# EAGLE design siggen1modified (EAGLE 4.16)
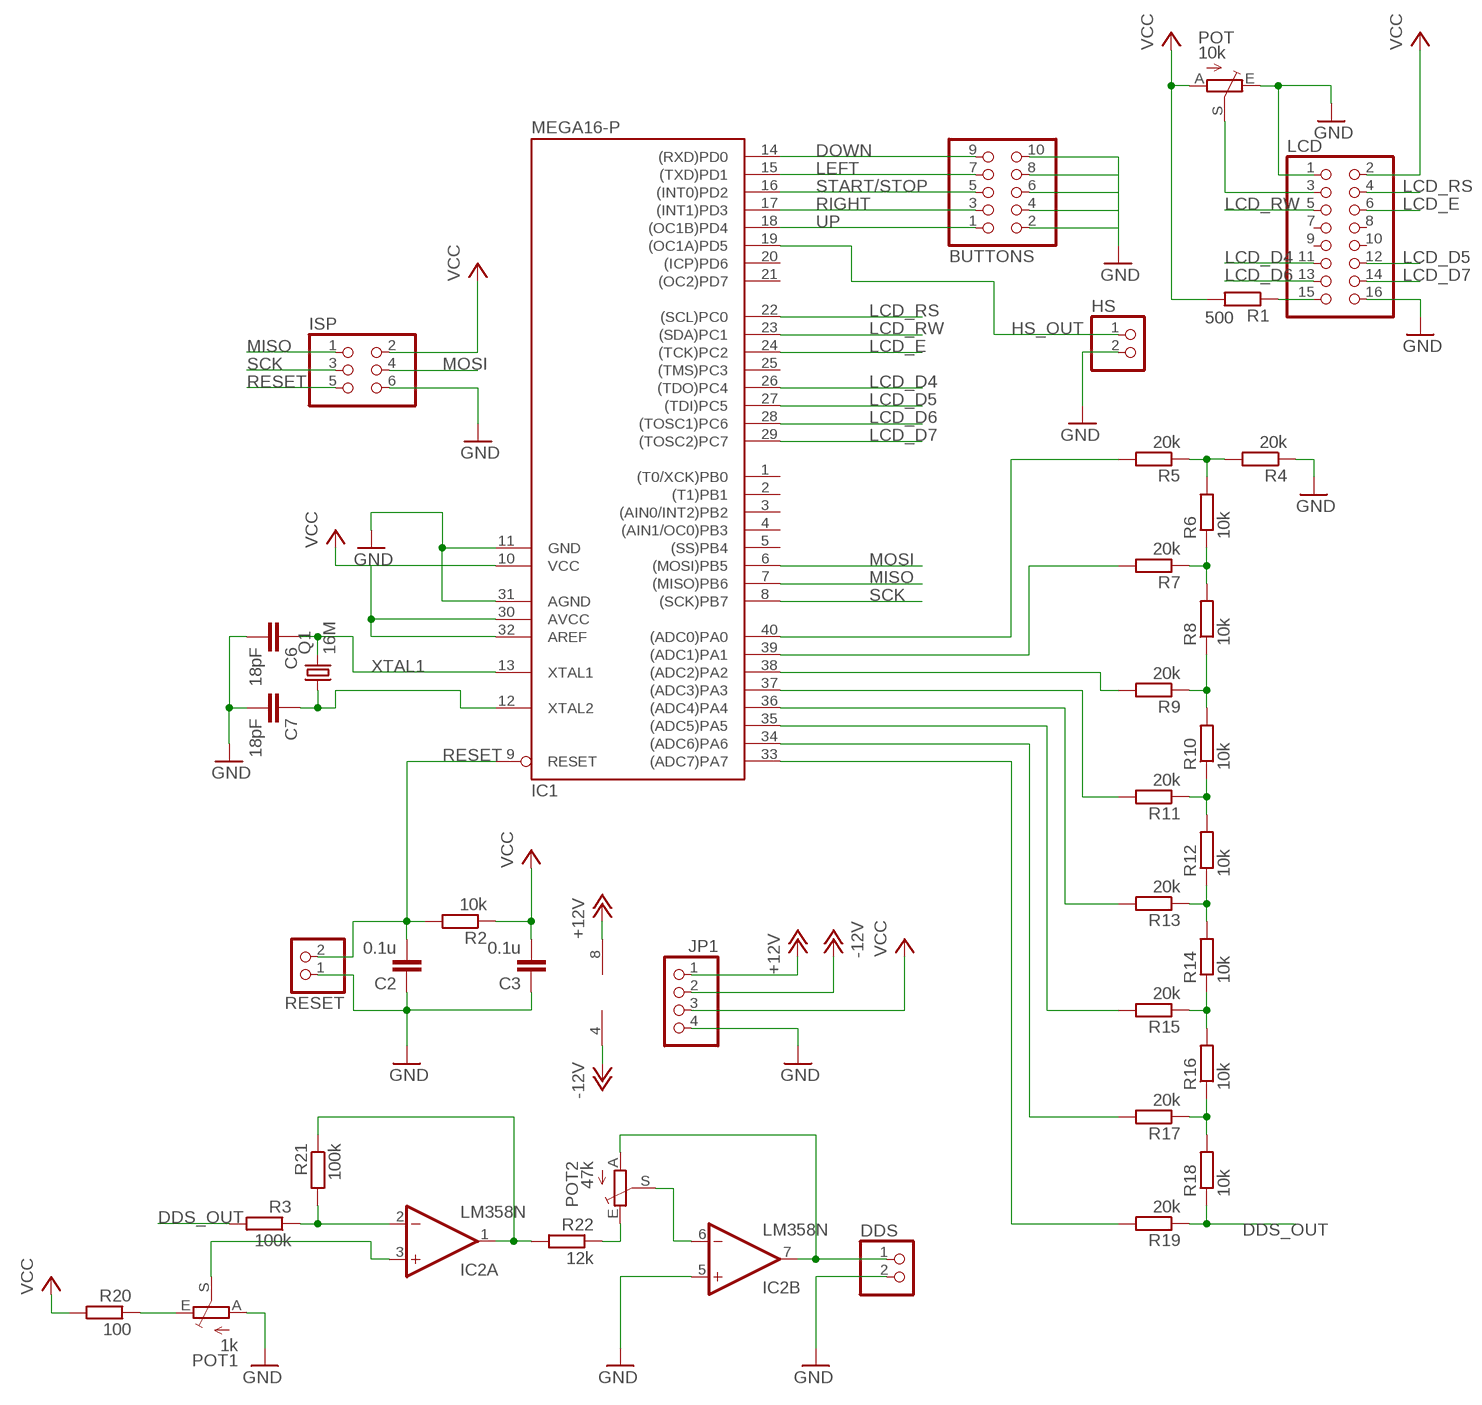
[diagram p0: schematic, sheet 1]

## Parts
BUTTONS  PINHD-2X5  [2X05]
C2  0.1u  C-EUC0805  [C0805]
C3  0.1u  C-EUC0805  [C0805]
C6  18pF  C-EUC0805  [C0805]
C7  18pF  C-EUC0805  [C0805]
DDS  PINHD-1X2  [1X02]
HS  PINHD-1X2  [1X02]
IC1  MEGA16-P  [DIL40]
IC2  LM358N  [DIL08]
ISP  PINHD-2X3  [2X03]
JP1  PINHD-1X4  [1X04]
LCD  PINHD-2X8  [2X08]
POT  10k  TRIM_EU-B64W  [B64W]
POT1  1k  TRIM_EU-B64W  [B64W]
POT2  47k  TRIM_EU-B64W  [B64W]
Q1  16M  CRYTALHC49S  [HC49/S]
R1  500  R-EU_M0805  [M0805]
R2  10k  R-EU_R0805  [R0805]
R3  100k  R-EU_M0805  [M0805]
R4  20k  R-EU_M0805  [M0805]
R5  20k  R-EU_M0805  [M0805]
R6  10k  R-EU_M0805  [M0805]
R7  20k  R-EU_M0805  [M0805]
R8  10k  R-EU_M0805  [M0805]
R9  20k  R-EU_M0805  [M0805]
R10  10k  R-EU_M0805  [M0805]
R11  20k  R-EU_M0805  [M0805]
R12  10k  R-EU_M0805  [M0805]
R13  20k  R-EU_M0805  [M0805]
R14  10k  R-EU_M0805  [M0805]
R15  20k  R-EU_M0805  [M0805]
R16  10k  R-EU_M0805  [M0805]
R17  20k  R-EU_M0805  [M0805]
R18  10k  R-EU_M0805  [M0805]
R19  20k  R-EU_M0805  [M0805]
R20  100  R-EU_M0805  [M0805]
R21  100k  R-EU_M0805  [M0805]
R22  12k  R-EU_M0805  [M0805]
RESET  PINHD-1X2  [1X02]

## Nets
+12V: IC2.8(P:V+) JP1.1
-12V: IC2.4(P:V-) JP1.2
DDS_OUT: R3.2 R18.1 R19.1
DOWN: BUTTONS.9 IC1.14((RXD)PD0)
GND: BUTTONS.2 BUTTONS.4 BUTTONS.6 BUTTONS.8 BUTTONS.10 C2.1 C3.1 C6.2 C7.2 DDS.2 HS.2 IC1.11(GND) IC1.31(AGND) IC2.5(B:+IN) ISP.6 JP1.4 LCD.1 LCD.16 POT1.A POT.E R4.1 RESET.1
HS_OUT: HS.1 IC1.19((OC1A)PD5)
LCD_D4: IC1.26((TDO)PC4) LCD.11
LCD_D5: IC1.27((TDI)PC5) LCD.12
LCD_D6: IC1.28((TOSC1)PC6) LCD.13
LCD_D7: IC1.29((TOSC2)PC7) LCD.14
LCD_E: IC1.24((TCK)PC2) LCD.6
LCD_RS: IC1.22((SCL)PC0) LCD.4
LCD_RW: IC1.23((SDA)PC1) LCD.5
LEFT: BUTTONS.7 IC1.15((TXD)PD1)
MISO: IC1.7((MISO)PB6) ISP.1
MOSI: IC1.6((MOSI)PB5) ISP.4
N$1: IC1.40((ADC0)PA0) R5.2
N$2: LCD.3 POT.S
N$3: IC2.2(A:-IN) R3.1 R21.2
N$5: LCD.15 R1.1
N$6: IC1.39((ADC1)PA1) R7.2
N$7: IC1.33((ADC7)PA7) R19.2
N$8: IC1.34((ADC6)PA6) R17.2
N$9: IC1.35((ADC5)PA5) R15.2
N$10: IC1.36((ADC4)PA4) R13.2
N$11: IC1.37((ADC3)PA3) R11.2
N$12: IC1.38((ADC2)PA2) R9.2
N$13: POT2.E R22.1
N$14: IC2.3(A:+IN) POT1.S
N$15: R4.2 R5.1 R6.2
N$16: IC2.1(A:OUT) R21.1 R22.2
N$17: POT1.E R20.1
N$18: R6.1 R7.1 R8.2
N$19: DDS.1 IC2.7(B:OUT) POT2.A
N$20: R8.1 R9.1 R10.2
N$21: R10.1 R11.1 R12.2
N$22: R12.1 R13.1 R14.2
N$23: R14.1 R15.1 R16.2
N$24: R16.1 R17.1 R18.2
N$25: IC2.6(B:-IN) POT2.S
N$29: C7.1 IC1.12(XTAL2) Q1.1
RESET: C2.2 IC1.9(RESET) ISP.5 R2.2 RESET.2
RIGHT: BUTTONS.3 IC1.17((INT1)PD3)
SCK: IC1.8((SCK)PB7) ISP.3
START/STOP: BUTTONS.5 IC1.16((INT0)PD2)
UP: BUTTONS.1 IC1.18((OC1B)PD4)
VCC: C3.2 IC1.10(VCC) IC1.30(AVCC) IC1.32(AREF) ISP.2 JP1.3 LCD.2 POT.A R1.2 R2.1 R20.2
XTAL1: C6.1 IC1.13(XTAL1) Q1.2
Unconnected: IC1.1((T0/XCK)PB0) IC1.2((T1)PB1) IC1.3((AIN0/INT2)PB2) IC1.4((AIN1/OC0)PB3) IC1.5((SS)PB4) IC1.20((ICP)PD6) IC1.21((OC2)PD7) IC1.25((TMS)PC3) LCD.7 LCD.8 LCD.9 LCD.10

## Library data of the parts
BUTTONS = pinhead:PINHD-2X5: PIN HEADER
C2 C3 C6 C7 = rcl:C-EU: CAPACITOR, European symbol
DDS HS RESET = pinhead:PINHD-1X2: PIN HEADER
IC1 = atmel:MEGA16-P: MICROCONTROLLER 16 Kbytes FLASH 1 kbytes SRAM 512 bytes EEPROM USART 8-channel 10 bit ADC Source: avr.lbr
IC2 = linear:LM358: OP AMP also LM158; LM258; LM2904 Source: http://cache.national.com/ds/LM/LM158.pdf
ISP = pinhead:PINHD-2X3: PIN HEADER
JP1 = pinhead:PINHD-1X4: PIN HEADER
LCD = pinhead:PINHD-2X8: PIN HEADER
POT POT1 POT2 = pot:TRIM_EU-: POTENTIOMETER
Q1 = crystal:CRYTAL: CRYSTAL
R1-R22 = rcl:R-EU_: RESISTOR, European symbol

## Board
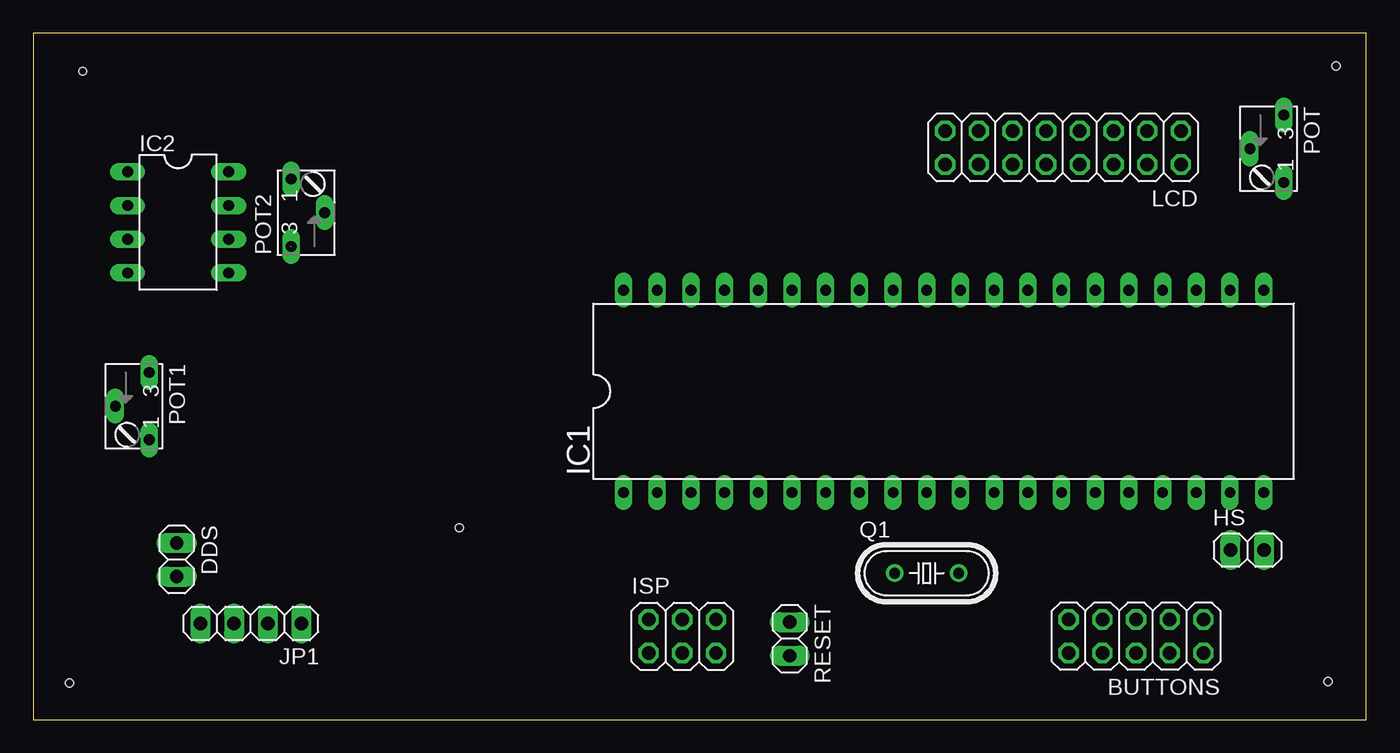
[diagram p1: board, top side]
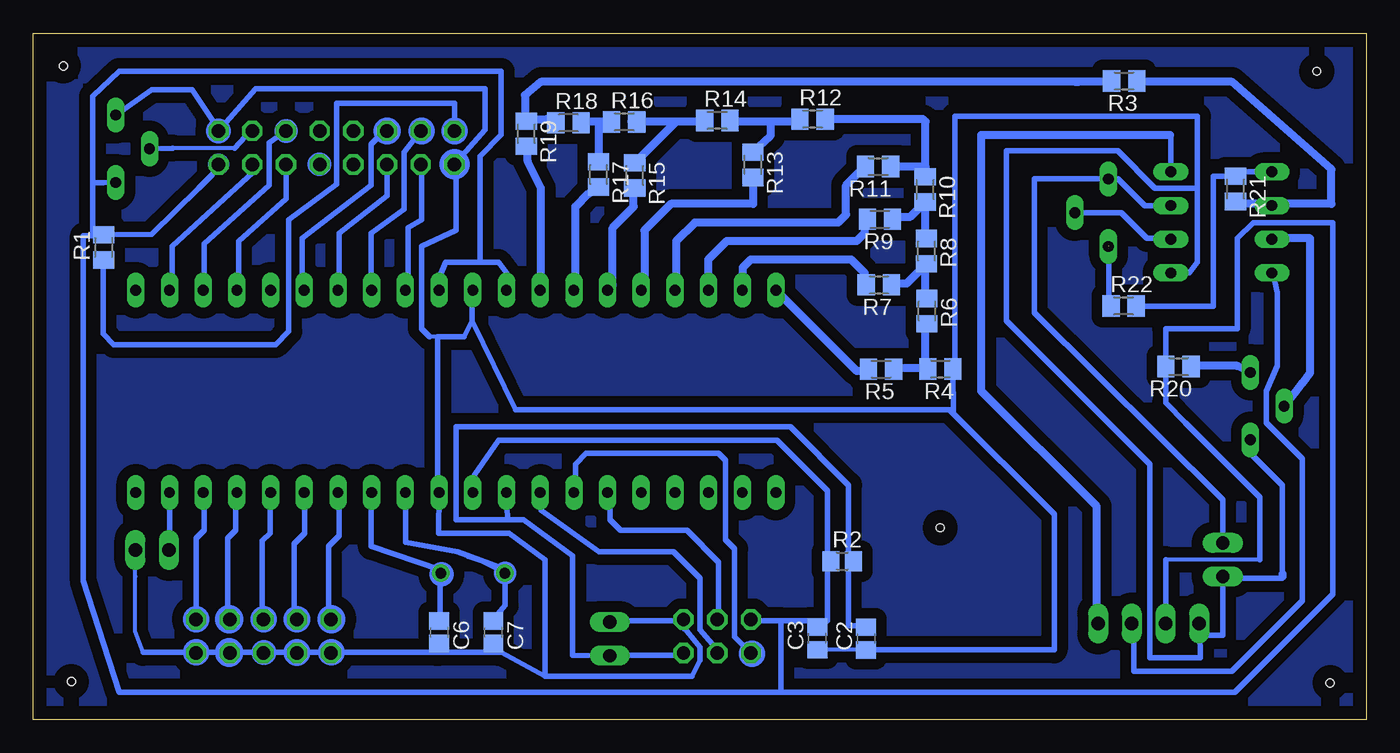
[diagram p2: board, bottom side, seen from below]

Size 100.51 x 51.74 mm. Coordinates in mm from the lower left corner, seen from the top.
Outline: 0,0 100.51,0 100.51,51.74 0,51.74 0,0
Copper layers (1*16): Top 0.035mm / dielectric 1.5mm / Bottom 0.035mm
Design rules "default": minimum track width 10mil, minimum drill 24mil, track to track 8mil, track to pad 8mil, pad to pad 8mil, via to via 8mil, smd to smd 8mil, copper to edge 40mil, drill to drill 8mil, minimum pad ring 10mil, minimum via ring 8mil, stop-mask expansion 4mil, vias tented up to drill 0mil, thermal gap 10mil
Holes 0.6 mm at 32.13,14.47 97.63,2.87 32.13,14.47 98.23,49.27 3.73,48.87 2.73,2.77 98.23,49.27 97.63,2.87

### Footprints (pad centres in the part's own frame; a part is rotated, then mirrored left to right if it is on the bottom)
2X05 = drill 1.016 octagon: 1 -5.08,-1.27; 2 -5.08,1.27; 3 -2.54,-1.27; 4 -2.54,1.27; 5 0,-1.27; 6 0,1.27; 7 2.54,-1.27; 8 2.54,1.27; 9 5.08,-1.27; 10 5.08,1.27
C0805 = smd 1.3 x 1.5: 1 -0.85,0; 2 0.85,0
1X02 = drill 1.016 long: 1 -1.27,0; 2 1.27,0
DIL40 = drill 0.813 long: 1 -24.13,-7.62; 2 -21.59,-7.62; 3 -19.05,-7.62; 4 -16.51,-7.62; 5 -13.97,-7.62; 6 -11.43,-7.62; 7 -8.89,-7.62; 8 -6.35,-7.62; 9 -3.81,-7.62; 10 -1.27,-7.62; 11 1.27,-7.62; 12 3.81,-7.62; 13 6.35,-7.62; 14 8.89,-7.62; 15 11.43,-7.62; 16 13.97,-7.62; 17 16.51,-7.62; 18 19.05,-7.62; 19 21.59,-7.62; 20 24.13,-7.62; 21 24.13,7.62; 22 21.59,7.62; 23 19.05,7.62; 24 16.51,7.62; 25 13.97,7.62; 26 11.43,7.62; 27 8.89,7.62; 28 6.35,7.62; 29 3.81,7.62; 30 1.27,7.62; 31 -1.27,7.62; 32 -3.81,7.62; 33 -6.35,7.62; 34 -8.89,7.62; 35 -11.43,7.62; 36 -13.97,7.62; 37 -16.51,7.62; 38 -19.05,7.62; 39 -21.59,7.62; 40 -24.13,7.62
DIL08 = drill 0.813 long: 1 -3.81,-3.81; 2 -1.27,-3.81; 3 1.27,-3.81; 4 3.81,-3.81; 5 3.81,3.81; 6 1.27,3.81; 7 -1.27,3.81; 8 -3.81,3.81
2X03 = drill 1.016 octagon: 1 -2.54,-1.27; 2 -2.54,1.27; 3 0,-1.27; 4 0,1.27; 5 2.54,-1.27; 6 2.54,1.27
1X04 = drill 1.016 long: 1 -3.81,0; 2 -1.27,0; 3 1.27,0; 4 3.81,0
2X08 = drill 1.016 octagon: 1 -8.89,-1.27; 2 -8.89,1.27; 3 -6.35,-1.27; 4 -6.35,1.27; 5 -3.81,-1.27; 6 -3.81,1.27; 7 -1.27,-1.27; 8 -1.27,1.27; 9 1.27,-1.27; 10 1.27,1.27; 11 3.81,-1.27; 12 3.81,1.27; 13 6.35,-1.27; 14 6.35,1.27; 15 8.89,-1.27; 16 8.89,1.27
B64W = drill 0.813 long: A 2.54,0; E -2.54,0; S 0,-2.54
HC49/S = drill 0.813 round: 1 -2.413,0; 2 2.413,0
M0805 = smd 1.3 x 1.6: 1 -0.95,0; 2 0.95,0
R0805 = smd 1.3 x 1.5: 1 -0.85,0; 2 0.85,0

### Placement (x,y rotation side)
BUTTONS  83.15,6.29 180 top
C2  37.72,6.11 90 bottom
C3  41.39,6.13 90 bottom
C6  69.9,6.59 270 bottom
C7  65.82,6.59 270 bottom
DDS  10.82,12.06 270 top
HS  91.54,12.78 0 top
IC1  68.64,24.75 0 top
IC2  10.93,37.48 270 top
ISP  48.94,6.29 0 top
JP1  16.41,7.25 180 top
LCD  77.64,43.11 180 top
POT  94.28,43.03 270 top
POT1  8.74,23.63 270 top
POT2  19.44,38.21 90 top
Q1  67.36,11.04 0 top
R1  95.2,35.6 90 bottom
R2  39.51,11.95 0 bottom
R3  18.26,48.14 180 bottom
R4  32.11,26.43 180 bottom
R5  36.59,26.41 180 bottom
R6  33.13,30.8 270 bottom
R7  36.75,32.77 180 bottom
R8  33.17,35.31 270 bottom
R9  36.67,37.71 180 bottom
R10  33.26,39.97 270 bottom
R11  36.81,41.69 180 bottom
R12  41.75,45.26 0 bottom
R13  46.25,41.82 270 bottom
R14  48.93,45.16 0 bottom
R15  55.15,41.02 270 bottom
R16  55.95,45.04 0 bottom
R17  57.89,41.1 270 bottom
R18  60.16,44.98 0 bottom
R19  63.33,44.16 270 bottom
R20  14.16,26.62 180 bottom
R21  9.86,40 270 bottom
R22  18.3,31.18 0 bottom
RESET  57.04,6.09 270 top

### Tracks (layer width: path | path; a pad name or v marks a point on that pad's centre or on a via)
+12V
  Bottom 0.406: IC2.8 14.73,44.07 14.78,44.07
  Bottom 0.61: 14.78,44.07 29.03,44.07 29.03,24.77 20.33,16.07 20.33,6.24 | 20.33,6.24 20.33,6.17 | JP1.1 20.33,6.24
-12V
  Bottom 0.305: 17.53,6.4 JP1.2 | 7.03,33.57 6.98,33.67
  Bottom 0.406: 17.53,6.4 17.53,3.67 10.13,3.67 4.83,8.97 4.83,19.67 7.53,22.37 7.53,24.77 6.73,26.67 6.73,32.17 7.03,33.57 IC2.4
DDS_OUT
  Bottom 0.61: R18.1 61.8,45.27 63.37,45.27 R19.1 63.29,45.07 63.43,45.07 63.43,47.07 62.23,48.07 21.93,48.07 | 21.93,48.07 21.74,48.07 | R3.2 19.28,48.07 21.93,48.07
DOWN
  Bottom 0.305: BUTTONS.9 78.23,7.72 | 77.43,17.07 77.47,17.07 IC1.14
  Bottom 0.406: 78.23,7.72 78.23,13.07 77.43,13.87 77.43,17.07
GND
  Bottom 0.254: C7.2 65.43,5.07 | C6.2 69.93,5.07 | 77.43,5.07 BUTTONS.10 | 51.23,6.67 51.43,6.87 | 31.03,27.17 R4.1
  Bottom 0.305: IC1.31 67.43,31.31 67.43,30.07 | 70.03,28.87 70.63,28.87 | 68.63,41.92 68.73,42.07 | 68.73,42.07 LCD.16 68.63,41.86 68.73,42.07 | LCD.1 86.73,44.77 | 68.73,42.07 68.73,41.87 | 88.43,5.07 BUTTONS.2 88.08,5.07 | 92.22,5.07 92.83,6.67 92.81,10.79 HS.2 | 85.83,5.07 85.83,4.88 BUTTONS.4 85.64,5.07 | 83.2,5.07 BUTTONS.6 83,5.07 | 80.43,4.87 80.46,5.07 BUTTONS.8 80.56,5.07 | 78.03,5.07 78.03,5.06 BUTTONS.10 | 51.43,7.47 51.43,7.51 ISP.6 | 56.93,7.47 RESET.1 | 12.53,6.37 12.53,6.42 JP1.4 | C3.1 41.43,5.27 | C3.1 | C3.1 C2.1 37.63,5.17
  Bottom 0.406: 8.83,20.17 6.33,17.67 6.33,10.97 6.33,10.67 10.93,10.67 10.93,10.79 DDS.2 10.83,6.37 12.53,6.37 | 6.33,10.8 6.33,10.77 | 67.43,30.07 68.03,28.87 70.03,28.87 70.03,18.27 IC1.11 69.93,14.07 64.63,14.07 61.93,12.07 61.93,3.27 | 70.63,28.87 71.23,29.47 71.23,35.67 68.63,36.87 68.63,41.86 68.63,41.92 | POT.E 91.58,47.47 88.53,47.47 86.73,44.77 | LCD.1 83.74,47.57 66.43,47.57 66.43,44.47 68.73,41.87 | 88.43,5.07 92.22,5.07 | 85.83,5.07 88.08,5.07 | 83.2,5.07 85.64,5.07 | 80.46,5.07 83,5.07 | 78.03,5.07 80.46,5.07 | 80.46,5.07 80.56,5.07 | 51.43,7.47 56.93,7.47 | R4.1 31.13,23.1 31.43,23.37 | 31.43,23.37 23.53,15.47 23.53,5.27 C2.1 | 65.43,5.07 69.93,5.07 | C6.2 70.13,5.07 69.93,5.07 | 69.93,5.07 77.43,5.07 | 51.23,6.67 50.23,5.47 50.23,4.47 50.83,3.27 61.93,3.27 | 61.93,3.27 65.23,5.07 C7.2 | 51.43,6.87 ISP.6 | 12.73,40.07 12.73,34.47 13.33,33.67 IC2.5 14.83,33.67 | 12.73,40.07 12.73,45.47 31.03,45.47 31.03,27.17 | 12.73,40.07 15.93,40.07 18.73,42.87 27.13,42.87 27.13,30.07 16.33,19.27 16.33,4.67 12.53,4.67 12.53,5.17 JP1.4 | 67.43,30.07 67.43,31.47 IC1.31 | 67.43,30.07 64.13,23.37 31.43,23.37
  Bottom 0.61: POT1.A 8.83,20.38 8.83,20.17 | 6.33,10.97 6.33,10.8
HS_OUT
  Bottom 0.305: 90.23,12.77 90.23,13.04 HS.1
  Bottom 0.406: 90.23,12.77 IC1.19
LCD_D4
  Bottom 0.305: IC1.26 80.23,32.53 | 73.63,44.77 73.74,44.47 LCD.11
  Bottom 0.406: 80.23,32.53 80.23,36.27 75.03,40.27 75.03,43.37 73.63,44.77
LCD_D5
  Bottom 0.305: IC1.27 77.43,32.47 | 73.83,41.77 73.8,41.77 LCD.12
  Bottom 0.406: 77.43,32.47 77.43,36.67 73.83,39.47 73.83,41.77
LCD_D6
  Bottom 0.305: IC1.28 75.03,32.41 | 71.23,44.47 71.23,44.44 LCD.13
  Bottom 0.406: 75.03,32.41 75.03,36.67 72.53,38.47 72.53,42.77 71.23,44.47
LCD_D7
  Bottom 0.305: IC1.29 72.23,32.59 | 71.23,41.8 LCD.14
  Bottom 0.406: 72.23,32.59 72.23,37.07 71.23,37.67 71.23,41.8
LCD_E
  Bottom 0.305: IC1.24 85.03,32.49 | 81.43,41.86 LCD.6
  Bottom 0.406: 85.03,32.49 85.03,36.07 81.43,39.27 81.43,41.86
LCD_RS
  Bottom 0.305: IC1.22 90.03,32.57 | 83.93,41.77 83.96,41.87 LCD.4
  Bottom 0.406: 90.03,32.57 90.03,35.67 83.93,41.27 83.93,41.77
LCD_RW
  Bottom 0.305: IC1.23 87.63,32.43 | 81.43,44.37 LCD.5
  Bottom 0.406: 87.63,32.43 87.63,35.87 82.73,40.27 82.73,43.47 81.43,44.37
LEFT
  Bottom 0.305: BUTTONS.7 80.83,7.78 | 80.03,17.09 IC1.15
  Bottom 0.406: 80.83,7.78 80.83,13.27 80.03,14.07 80.03,17.09
MISO
  Bottom 0.305: 59.63,17.25 IC1.7 | 46.43,5.07 46.43,5.05 ISP.1
  Bottom 0.406: 59.63,17.25 59.63,19.27 58.83,20.07 48.83,20.07 48.33,19.57 48.33,13.57 47.63,12.87 47.63,6.27 46.43,5.07
MOSI
  Bottom 0.305: 57.03,16.95 IC1.6 | 48.83,7.67 ISP.4
  Bottom 0.406: 57.03,16.95 57.03,15.07 56.23,14.27 51.23,14.27 48.83,11.87 48.83,7.67
N$1
  Bottom 0.61: R5.2 37.43,26.3 37.43,26.27 38.41,26.27 IC1.40
N$2
  Bottom 0.305: 85.33,43.07 90,43.07 | LCD.3 84.03,44.42 84.03,44.27 84.13,44.37
  Bottom 0.406: 90,43.07 POT.S | 84.13,44.37 85.33,43.07
N$3
  Bottom 0.406: IC2.2 7.13,38.77 7.13,38.87
  Bottom 0.61: R21.2 10.13,38.92 10.13,38.87 7.13,38.87 | R3.1 17.24,48.07 10.13,48.07 2.63,41.47 2.63,38.87 7.13,38.87 | 7.13,38.87 7.1,38.87
N$4
  pour Bottom (isolate 0.813): 0.23,51.67 100.43,51.87 100.43,0.07 0.03,0.07
N$5
  Bottom 0.305: R1.1 95.28,34.57 95.13,34.17 95.23,34.57 95.23,34.17
  Bottom 0.406: LCD.15 68.74,46.47 77.63,46.47 77.63,40.37 81.23,37.67 81.23,29.27 82.23,28.27 94.43,28.27 95.23,29.07 95.23,34.17
N$6
  Bottom 0.61: IC1.39 47.03,32.39 47.03,34.07 46.43,34.67 38.83,34.67 37.83,33.67 37.83,32.87 37.8,32.87 R7.2
N$7
  Bottom 0.61: IC1.33 62.23,32.43 62.23,40.07 63.23,42.07 63.23,43.11 R19.2
N$8
  Bottom 0.61: IC1.34 59.63,32.49 59.63,38.67 58.63,39.67 58.57,39.67 R17.2
N$9
  Bottom 0.61: IC1.35 56.83,32.75 56.83,37.07 55.23,38.67 55.23,40.07 R15.2
N$10
  Bottom 0.61: IC1.36 54.43,32.61 54.43,36.87 52.43,38.87 46.23,38.87 46.23,40.85 R13.2
N$11
  Bottom 0.61: IC1.37 52.03,32.47 52.03,36.07 50.63,37.47 39.83,37.47 39.23,38.07 39.23,40.27 38.03,41.47 38.03,41.67 37.78,41.67 R11.2
N$12
  Bottom 0.61: IC1.38 49.63,32.41 49.63,34.67 48.23,36.07 38.43,36.07 37.83,36.67 37.83,37.5 R9.2
N$13  (1 unrouted)
  Bottom 0.406: 19.43,35.65 POT2.E 19.43,31.18 R22.1
N$14
  Bottom 0.406: 7.13,36.17 7.12,36.18 | 7.12,36.18 IC2.3 | 7,36.27 7.03,36.27 7.12,36.18
  Bottom 0.61: 7,36.27 4.23,36.27 4.23,26.17 4.83,25.37 5.44,24.57 POT1.S
N$15
  Bottom 0.61: R5.1 35.58,26.47 33.1,26.47 R4.2 33.23,26.6 33.23,29.75 R6.2
N$16
  Bottom 0.406: IC2.1 9.83,41.29 9.83,40.95 R21.1 11.53,40.95 11.53,31.17 17.23,31.17 17.23,31.18 R22.2
N$17
  Bottom 0.61: R20.1 13.16,26.67 9.74,26.67 POT1.E
N$18
  Bottom 0.61: R7.1 35.83,32.8 35.83,32.87 34.66,32.87 R8.2 33.23,34.3 33.23,31.85 R6.1
N$19
  Bottom 0.406: IC2.7 16.71,38.75 18.73,40.77 19.53,40.77 | 19.53,40.77 POT2.A 19.44,40.68 | DDS.1 10.82,16.56 25.03,30.67 25.03,40.77 19.53,40.77 | 19.44,40.68 19.43,40.67 | 19.53,40.77 19.44,40.68
N$20
  Bottom 0.61: R8.1 33.23,36.32 33.23,38.99 R10.2 34.41,37.87 35.63,37.87 35.63,37.8 R9.1
N$21
  Bottom 0.61: R12.2 39.59,45.27 33.43,45.27 33.23,45.07 33.23,41.67 | 33.23,40.89 33.23,40.67 | R10.1 33.23,40.89 | 33.23,40.89 33.23,41.67 | R11.1 35.84,41.67 33.23,41.67
N$22
  Bottom 0.61: 42.91,45.07 R12.1 42.89,45.07 42.91,45.07 | R13.1 44.93,43.99 44.93,45.07 | R14.2 47.89,45.07 44.93,45.07 | 42.91,45.07 44.93,45.07
N$23
  Bottom 0.61: R15.1 52.05,45.07 49.97,45.07 | R16.2 55.43,45.07 49.97,45.07 | R14.1 49.97,45.07
N$24
  Bottom 0.61: 57.83,45.07 57.67,45.07 R16.1 | R17.1 57.83,42.31 57.83,45.07 | R18.2 59.3,45.07 57.83,45.07
N$25
  Bottom 0.406: POT2.S 18.47,38.21 16.53,36.27 14.73,36.27 14.74,36.26 IC2.6
N$29
  Bottom 0.305: Q1.1 66.58,11.87 67.73,12.27 65.03,11.37 | C7.1 65.83,7.55
  Bottom 0.406: IC1.12 72.43,15.51 72.43,13.37 68.53,12.67 65.03,11.37 | Q1.1 64.93,8.62 65.83,7.55
RESET
  Bottom 0.254: C2.2 37.83,7.07
  Bottom 0.305: 51.43,4.87 51.43,4.97 ISP.5 | RESET.2 56.99,4.87
  Bottom 0.406: 56.99,4.87 51.43,4.87 | 64.73,15.07 63.53,15.07 59.83,12.37 59.83,4.87 RESET.2 | 64.73,15.07 IC1.9 | 64.73,15.07 68.63,15.07 68.63,22.07 43.43,22.07 39.03,17.67 39.03,11.67 | 37.83,7.07 39.03,7.07 39.03,11.67 | R2.2 38.63,11.95 38.63,11.67 39.03,11.67
RIGHT
  Bottom 0.305: BUTTONS.3 85.83,7.7 | 85.23,17.07 85.21,17.07 IC1.17
  Bottom 0.406: 85.83,7.7 85.83,13.67 85.23,14.27 85.23,17.07
SCK
  Bottom 0.305: IC1.8 62.23,17.07 62.23,15.77 | 48.83,5.07 48.89,5.07 | 48.89,5.07 ISP.3 | 48.89,5.07 48.83,5.17
  Bottom 0.406: 62.23,15.77 57.83,12.67 52.23,12.67 50.23,10.67 50.23,6.77 48.83,5.17
START/STOP
  Bottom 0.305: BUTTONS.5 83.23,7.64 | 82.63,17.11 IC1.16
  Bottom 0.406: 83.23,7.64 83.23,13.47 82.63,14.07 82.63,17.11
UP
  Bottom 0.305: 87.63,17.07 IC1.18
  Bottom 0.406: BUTTONS.1 88.23,13.67 87.63,14.27 87.63,17.07
VCC
  Bottom 0.254: 40.63,7.47 40.83,7.47 C3.2 42.03,7.47 | 67.23,18.47 67.23,18.27 | 45.83,7.47 ISP.2 | 95.73,36.47 R1.2
  Bottom 0.305: 96.03,36.77 95.08,36.87 R1.2 | 86.53,41.87 LCD.2 | 15.13,6.54 JP1.3 | 8.03,12.07 15.13,12.07
  Bottom 0.406: 96.03,36.77 96.03,40.44 POT.A 96.03,40.47 96.03,46.97 94.03,48.87 65.23,48.87 65.23,44.07 66.83,42.47 66.83,34.47 | R1.2 91.58,36.57 88.03,40.07 87.03,41.07 86.53,41.87 | 8.03,12.07 8.03,16.77 13.63,22.37 15.13,23.9 R20.2 15.11,28.45 15.13,29.47 9.73,29.47 9.73,36.27 8.53,37.47 2.53,37.47 2.53,9.47 9.93,2.07 44.13,2.07 | 15.13,12.07 15.13,6.54 | 67.23,18.47 65.43,21.07 44.43,21.07 40.63,17.27 40.63,12.47 40.43,12.47 40.43,11.95 | 67.23,18.27 IC1.10 | 44.13,7.47 42.03,7.47 | 44.13,7.47 45.83,7.47 | 66.83,34.47 65.43,34.47 64.83,33.67 IC1.32 | 66.83,34.47 69.43,34.47 69.83,33.47 IC1.30 | 44.13,2.07 94.03,2.07 96.73,10.47 96.73,36.47 95.73,36.47 | 40.63,7.47 40.63,11.97 40.43,11.95 | 40.43,11.95 40.63,11.95 40.63,7.47 | 40.43,11.95 R2.1 | 44.13,7.47 40.63,7.47 | 44.13,2.07 44.13,7.47
XTAL1
  Bottom 0.305: 75.03,17.09 IC1.13 | C6.1 69.83,7.11 | Q1.2 69.83,11.38
  Bottom 0.406: 69.83,11.3 Q1.2 | 75.03,17.09 75.03,13.07 69.83,11.3 | 69.83,7.11 69.83,11.3 | 69.83,11.3 69.83,11.38
(copper drawn outside any net)
  shapes: Bottom circle x55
